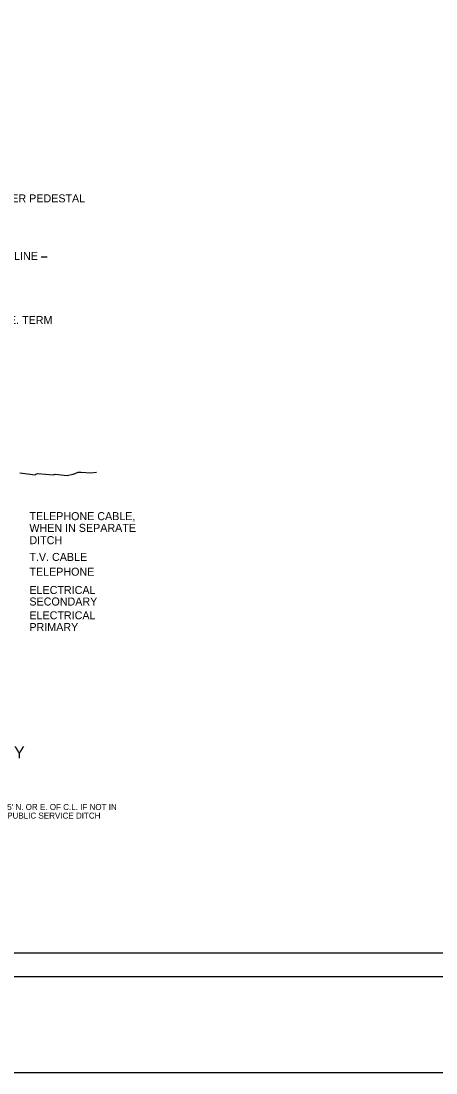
# Model space of a CAD drawing. Extents: x 524397 to 525117, y 3701341 to 3701821.
# Drawn here: x 524603 to 524706.5, y 3701341 to 3701603.7 of the extents above; entities that cross this region are included whole.
import ezdxf

# ---------------------------------------------------------------- set-up
doc = ezdxf.new("R2010")
doc.units = 0
for name, color, linetype in [('Level 1', 7, 'Continuous'), ('Level 11', 7, 'Continuous'), ('Level 9', 7, 'Continuous'), ('Pam batch print border', 7, 'Continuous')]:
    doc.layers.add(name, color=color, linetype=linetype)

msp = doc.modelspace()

# ---------------------------------------------------------------- linework, layer by layer
at = {"layer": 'Level 1'}
for p, q in [((524607.96, 3701544.88), (524609.49, 3701544.88)), ((524602.62, 3701490.9), (524606.46, 3701490.38)), ((524606.46, 3701490.38), (524606.63, 3701490.55)), ((524606.63, 3701490.55), (524607.15, 3701490.73)), ((524607.15, 3701490.73), (524610.99, 3701490.38)), ((524610.99, 3701490.38), (524611.51, 3701490.55)), ((524611.51, 3701490.55), (524614.47, 3701490.2)), ((524614.47, 3701490.2), (524615.87, 3701490.55)), ((524615.87, 3701490.55), (524616.04, 3701490.55)), ((524616.04, 3701490.55), (524617.26, 3701491.07)), ((524617.26, 3701491.07), (524617.96, 3701491.07)), ((524617.96, 3701491.07), (524620.4, 3701490.9)), ((524620.4, 3701490.9), (524621.79, 3701491.07)), ((524442.4, 3701370.98), (525097.4, 3701370.98))]:
    msp.add_line(p, q, dxfattribs=at)
at = {"layer": 'Level 9'}
msp.add_lwpolyline([(524396.79, 3701820.98), (525116.79, 3701820.98), (525116.79, 3701340.98), (524396.79, 3701340.98)], close=True, dxfattribs=at)
at = {"layer": 'Pam batch print border'}
msp.add_lwpolyline([(524433.4, 3701796.98), (525105.4, 3701796.98), (525105.4, 3701364.98), (524433.4, 3701364.98)], close=True, dxfattribs=at)
msp.add_lwpolyline([(524433.4, 3701796.98), (525105.4, 3701796.98), (525105.4, 3701364.98), (524433.4, 3701364.98)], close=True, dxfattribs=at)

# ---------------------------------------------------------------- texts
at = {"layer": 'Level 1'}
for s, height, p in [('LOT LINE', 2, (524595.28, 3701544.08)), ('TELEPHONE CABLE,', 2, (524605.05, 3701479.07)), ('WHEN IN SEPARATE', 2, (524605.05, 3701476.14)), ('DITCH', 2, (524605.05, 3701473.07)), ('T.V. CABLE', 2, (524605.05, 3701468.88)), ('TELEPHONE', 2, (524605.05, 3701465.19)), ('ELECTRICAL', 2, (524605.05, 3701460.62)), ('SECONDARY', 2, (524605.05, 3701457.74)), ('ELECTRICAL', 2, (524605.05, 3701454.3)), ('PRIMARY', 2, (524605.05, 3701451.37)), ('CENTERLINE OF ALLEY', 3, (524558.17, 3701419.56)), ("5' N. OR E. OF C.L. IF NOT IN ", 1.5, (524599.5, 3701406.68)), ('PUBLIC SERVICE DITCH', 1.5, (524599.5, 3701404.52))]:
    msp.add_text(s, height=height, dxfattribs=at).set_placement(p)
at = {"layer": 'Level 11'}
for s, p in [('POWER PEDESTAL', (524594.14, 3701558.45)), ('TELE. TERM', (524595.05, 3701528.06))]:
    msp.add_text(s, height=2, dxfattribs=at).set_placement(p)

doc.saveas('drawing.dxf')
